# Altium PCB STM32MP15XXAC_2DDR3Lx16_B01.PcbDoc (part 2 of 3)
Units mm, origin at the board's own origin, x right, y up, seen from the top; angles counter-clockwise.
Board outline 89 x 120 mm, 4 copper layers (Top Layer, Signal Layer 1, Signal Layer 2, Bottom Layer), stack 1.571 mm thick; 152 components, 117 nets, 1047 pads, 460 vias.
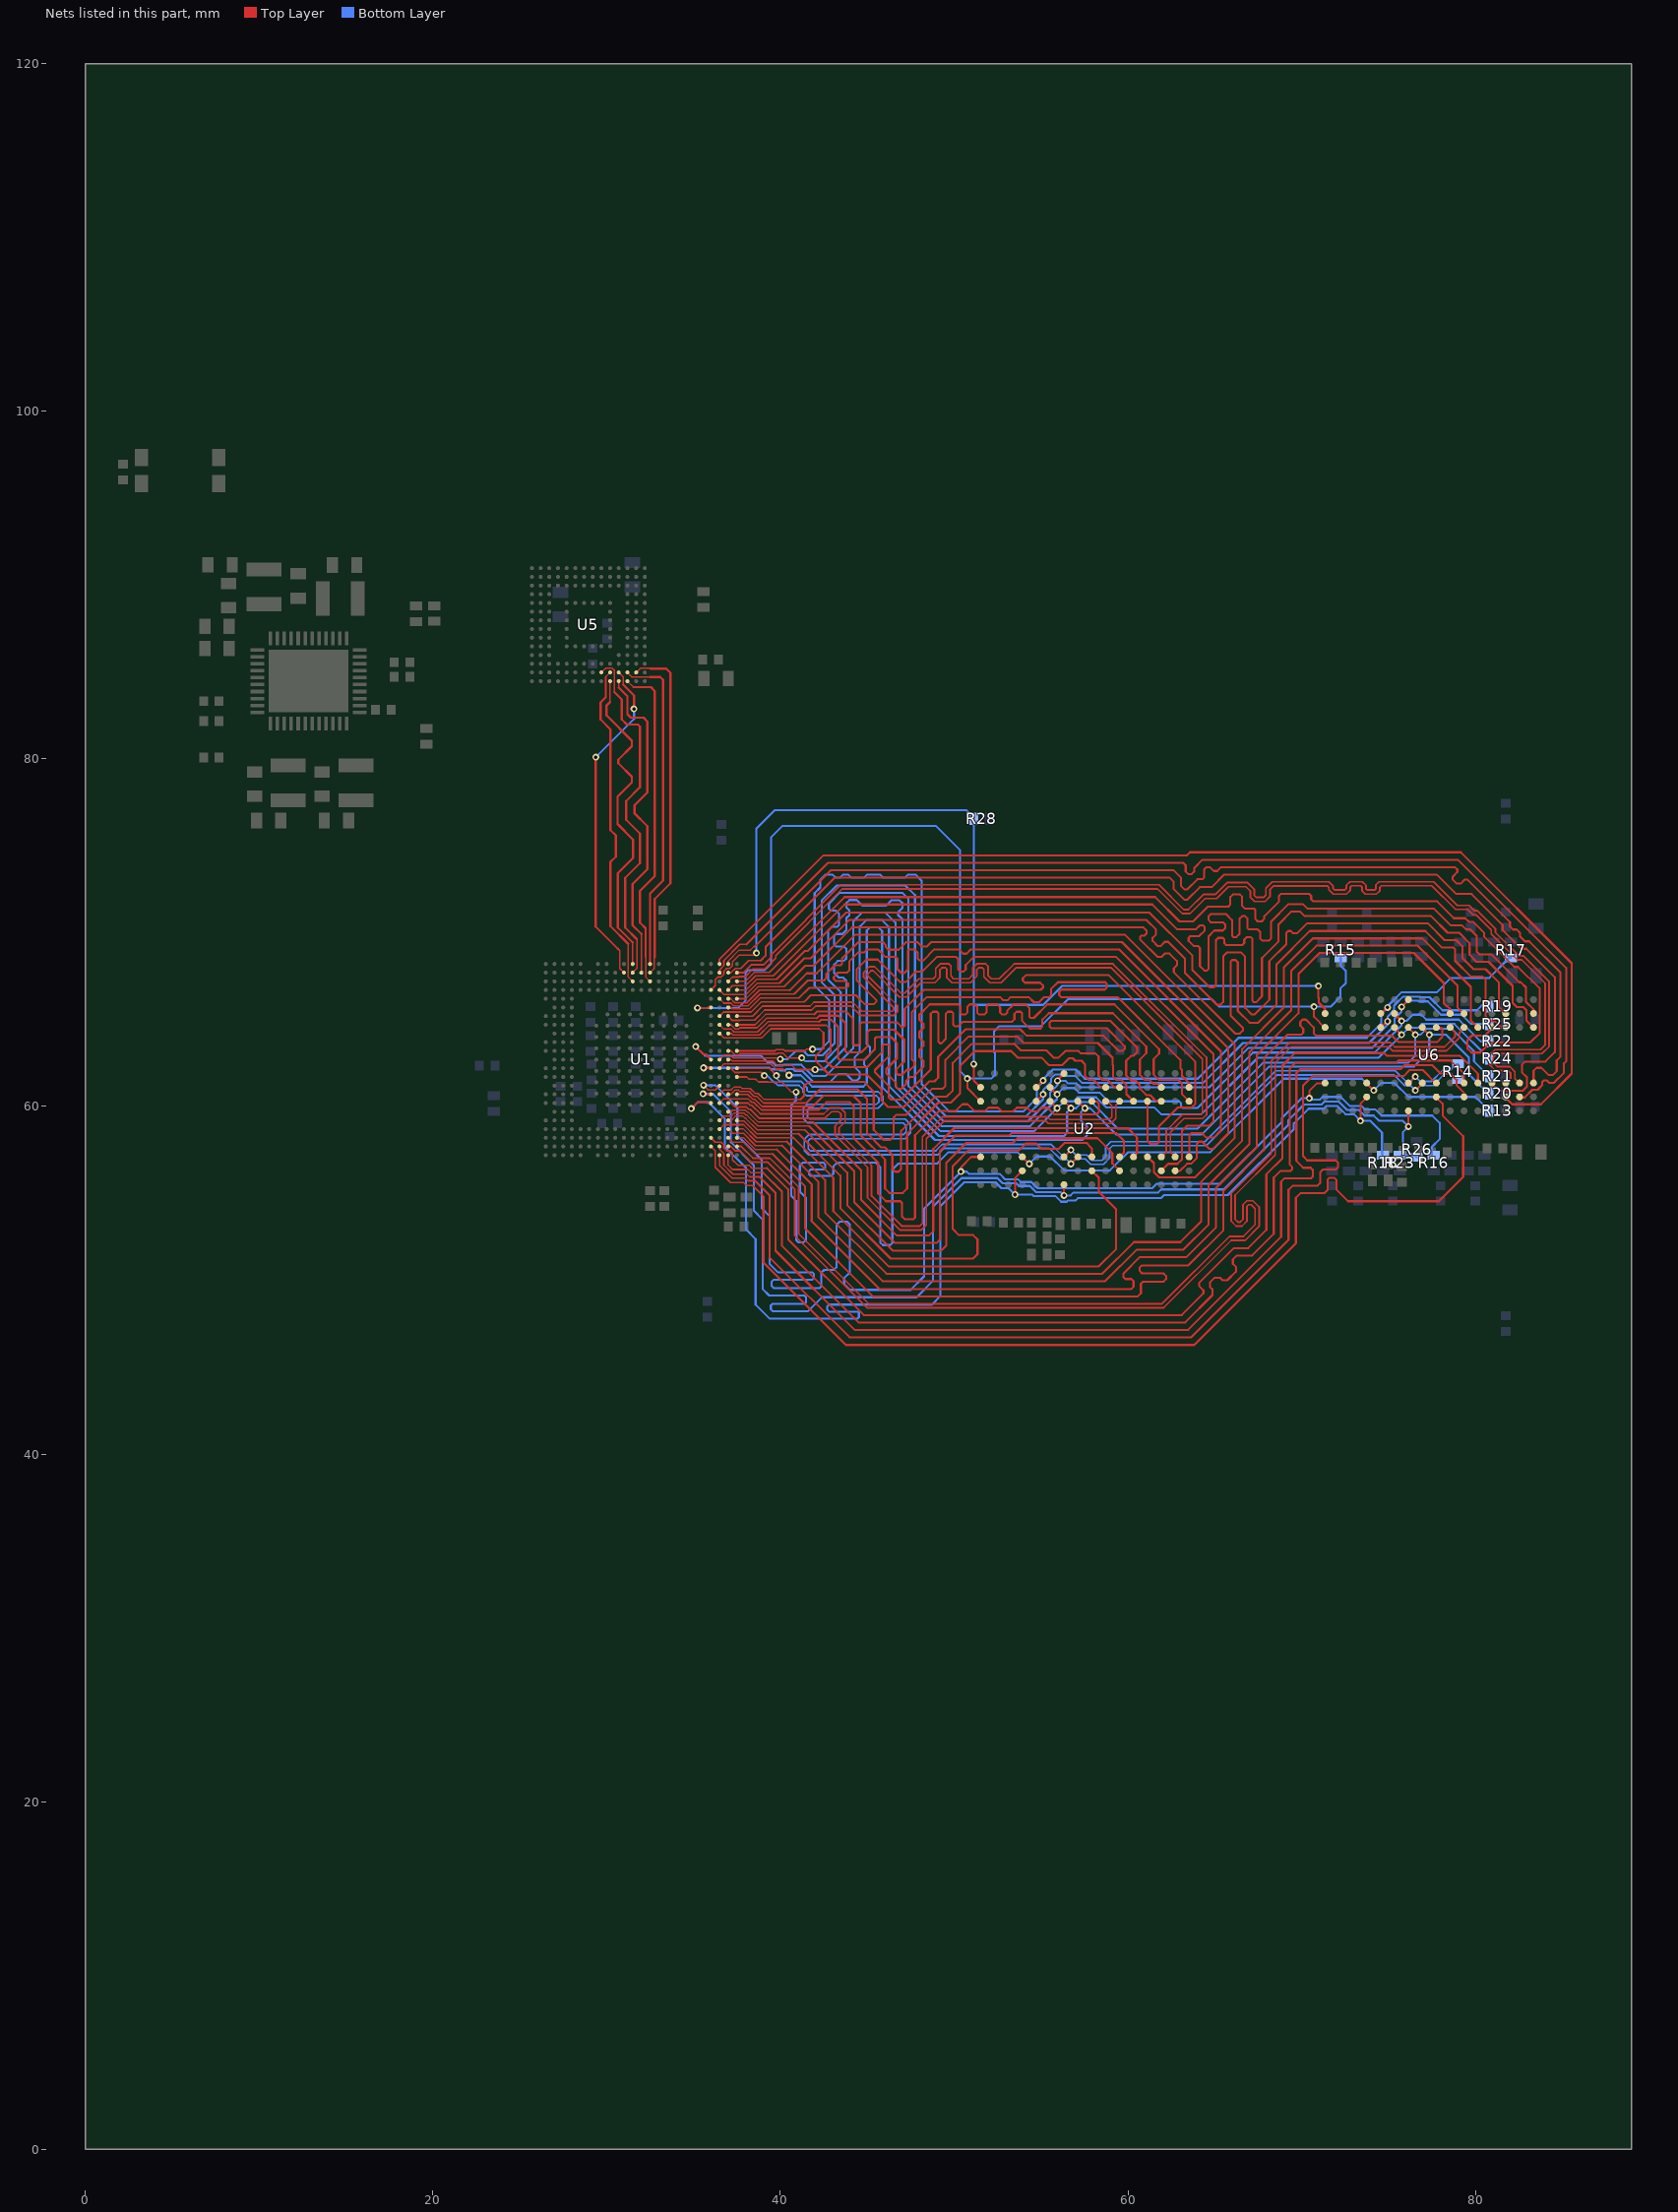
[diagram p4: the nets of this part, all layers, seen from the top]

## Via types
v1: diameter 0.4, hole 0.2, Top Layer to Bottom Layer, tented both sides, 302 vias
v2: diameter 0.6, hole 0.3, Top Layer to Bottom Layer, tented both sides, 80 vias
v3: diameter 0.25, hole 0.1, Top Layer to Signal Layer 1, tented top, 70 vias
v4: diameter 0.25, hole 0.1, Top Layer to Signal Layer 1, tented both sides, 6 vias
v5: diameter 0.25, hole 0.1, Top Layer to Bottom Layer, tented top, 2 vias

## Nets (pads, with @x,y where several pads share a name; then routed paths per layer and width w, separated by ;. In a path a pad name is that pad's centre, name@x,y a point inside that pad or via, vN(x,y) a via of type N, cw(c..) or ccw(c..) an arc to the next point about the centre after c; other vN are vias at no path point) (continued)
DDR_A12: R13.1 U1.P23 U2.N7 U6.N7 | length 74.8
  Top Layer w0.09: U1.P23@37.5,61.7 38.075,61.7 38.2,61.575 38.575,61.575 38.735,61.415 39.288,61.415 39.303,61.4 40.088,61.4 40.52,60.968 40.52,60.93 40.625,60.825 v1(40.9,60.825)
  Top Layer w0.12: U2.N7@53.925,57.1 v1(54.325,56.7) ; U6.N7@73.75,61.325 v1(74.15,60.925)
  Bottom Layer w0.12: v1(40.9,60.825) 40.9,60.35 40.625,60.075 40.625,54.85 40.925,54.55 40.925,52.3 41.05,52.175 41.325,52.175 41.475,52.325 41.475,54.75 41.125,55.1 41.125,56.6 41.3,56.775 42.475,56.775 42.575,56.675 42.575,56.475 42.475,56.375 41.75,56.375 41.65,56.275 41.65,56.1 41.75,56 42.925,56 43.05,56.125 43.05,56.55 43.275,56.775 45.5,56.775 45.75,56.525 45.75,52.175 45.9,52.025 46.325,52.025 46.45,52.15 46.45,56.375 46.8,56.725 49.025,56.725 49.675,57.375 53.65,57.375 v1(54.325,56.7) 54.75,57.125 55.525,57.125 56.325,56.325 58.975,56.325 60.025,57.375 64.75,57.375 68.975,61.6 73.475,61.6 v1(74.15,60.925) 74.575,61.35 75.35,61.35 76.15,60.55 80,60.55 R13.1@80.8,59.75
DDR_A13: R15.1 U1.F20 U2.T3 U6.T3 | length 70.3
  Top Layer w0.09: v1(35.225,65.675) 35.25,65.7 35.437,65.7 35.482,65.655 35.768,65.655 35.813,65.7 U1.F20@36,65.7
  Top Layer w0.12: v1(50.765,61.61) 50.765,61.06 U2.T3@51.525,60.3 ; v1(70.71,65.745) 70.71,65.165 U6.T3@71.35,64.525
  Bottom Layer w0.09: v1(35.225,65.675) 35.245,65.655 35.92,65.655
  Bottom Layer w0.12: 35.92,65.655 37.555,65.655 38,66.1 38,67.7 38.15,67.85 39.1,67.85 39.475,68.225 39.475,75.5 40.125,76.15 48.95,76.15 50.35,74.75 50.35,62.025 v1(50.765,61.61) 52.135,61.61 52.35,61.825 52.35,63.075 52.3,63.125 52.3,64.325 52.6,64.625 55,64.625 56.55,66.175 64.825,66.175 65.255,65.745 v1(70.71,65.745) 71.67,65.745 72.225,66.3 72.225,66.775 72.55,67.1 72.55,67.8 72.25,68.1 R15.1@72.25,68.55
DDR_A14: R16.1 U1.R21 U2.T7 U6.T7 | length 78.8
  Top Layer w0.09: 35.725,61.075 35.85,60.95 36.25,60.95 U1.R21@36.5,61.2
  Top Layer w0.12: v1(50.395,56.25) 50.395,56.51 50.985,57.1 U2.T7@51.525,57.1 ; v1@70.44,60.405 v1(70.44,60.475) 70.44,60.895 70.87,61.325 U6.T7@71.35,61.325
  Bottom Layer w0.12: v1(35.575,61.225) 36.25,61.225 37.525,59.95 37.525,58.325 38.925,56.925 38.925,54.15 39.375,53.7 39.375,50.95 39.875,50.45 41.85,50.45 41.925,50.375 41.925,50.125 41.825,50.025 39.6,50.025 39.5,49.925 39.5,49.675 39.625,49.55 42.25,49.55 42.35,49.65 42.35,50.425 42.525,50.6 43.075,50.6 43.225,50.75 43.225,53.175 43.425,53.375 43.85,53.375 44,53.225 44,50.45 43.675,50.125 43.675,49.775 44,49.45 47.5,49.45 48.275,50.225 48.275,54.13 v1(50.395,56.25) 50.725,56.25 50.85,56.125 52.625,56.125 52.95,55.8 53.689,55.8 53.839,55.65 54.45,55.65 54.8,55.3 61.4,55.3 61.65,55.55 65.3,55.55 68.875,59.125 68.875,59.35 70,60.475 v1(70.44,60.475) 70.51,60.405 71.062,60.405 71.212,60.555 72.245,60.555 72.765,60.035 73.44,60.035 73.65,59.825 74.25,59.825 74.6,59.475 77.525,59.475 77.95,59.05 77.95,58.125 77.5,57.675 R16.1@77.5,57.2
DDR_BA0: R17.1 U1.L23 U2.M2 U6.M2 | length 74.2
  Top Layer w0.09: U1.L23@37.5,63.2 39.697,63.2 39.762,63.265 40.188,63.265 40.253,63.2 41.4,63.2 41.5,63.3 v1(41.85,63.3)
  Top Layer w0.12: U2.M2@54.725,61.1 v1(55.125,61.5) ; U6.M2@74.55,65.325 v1@74.95,65.725
  Bottom Layer w0.12: v1(41.85,63.3) 42.35,63.3 42.8,63.75 42.8,66.125 41.975,66.95 41.975,72.275 42.3,72.6 42.3,73.05 42.6,73.35 43,73.35 43.175,73.175 43.45,73.175 43.625,73.35 43.9,73.35 44.075,73.175 44.825,73.175 45,73.35 45.725,73.35 45.9,73.175 47.175,73.175 47.35,73.35 47.775,73.35 48.125,73 48.125,61.3 49.7,59.725 54,59.725 54.75,60.475 54.75,61.064 55.125,61.439 v1(55.125,61.5) 55.125,61.575 55.675,62.125 57,62.125 57.525,61.6 64.025,61.6 66.375,63.95 73.75,63.95 74.575,64.775 74.575,65.314 v1@74.95,65.689 ; v1(74.95,65.7) 74.95,65.775 75.74,66.565 77.765,66.565 78.6,67.4 80.8,67.4 81.95,68.55 R17.1@82.05,68.55
DDR_BA1: R18.1 U1.U20 U2.N8 U6.N8 | length 69.7
  Top Layer w0.12: v1(34.875,59.875) 35.26,60.26 35.749,60.26 35.809,60.2 U1.U20@36,60.2 ; v1@53.505,54.939 53.505,55.88 U2.N8@53.925,56.3 ; v1(73.39,59.175) 73.39,60.165 U6.N8@73.75,60.525
  Bottom Layer w0.12: v1(34.875,59.875) 35.26,60.26 35.84,60.26 36.8,59.3 36.8,57.7 38.025,56.475 38.025,52.925 38.575,52.375 38.575,48.6 39.375,47.8 44.45,47.8 44.525,47.875 44.525,48.125 44.45,48.2 42.8,48.2 42.7,48.3 42.7,48.5 42.8,48.6 48.725,48.6 49.2,49.075 49.2,54.25 50.59,55.64 52.385,55.64 52.725,55.3 53.135,55.3 v1(53.505,54.93) 54.495,54.93 54.575,54.85 55.825,54.85 56.155,54.52 56.474,54.52 56.554,54.6 57,54.6 57.125,54.725 61.9,54.725 62.075,54.9 65.75,54.9 69.55,58.7 69.55,59.025 70.4,59.875 71.275,59.875 71.425,60.025 72.061,60.025 72.531,59.555 73.01,59.555 v1(73.39,59.175) 73.95,59.175 74.625,58.5 74.625,57.25 R18.1@74.675,57.2
DDR_BA2: R19.1 U1.M21 U2.M3 U6.M3 | length 72.3
  Top Layer w0.09: U1.M21@36.5,62.7 36.75,62.95 37.135,62.95 37.295,62.79 39.935,62.79 v1(40,62.725)
  Top Layer w0.12: U2.M3@54.725,60.3 v1@55.105,60.68 ; U6.M3@74.55,64.525 74.925,64.9 v1(74.95,64.9)
  Bottom Layer w0.12: v1(40,62.725) 40.425,62.725 40.9,63.2 41.334,63.2 41.594,62.94 42.415,62.94 43.125,63.65 43.125,66.4 42.375,67.15 42.375,71.844 43.251,72.72 47.193,72.72 47.75,72.163 47.75,61.225 49.55,59.425 54.125,59.425 55.125,60.425 v1(55.125,60.7) 55.125,60.95 55.59,61.415 55.59,61.624 55.801,61.835 56.099,61.835 56.184,61.75 56.975,61.75 57.375,61.35 64.325,61.35 66.625,63.65 73.875,63.65 74.95,64.725 v1(74.95,64.9) 74.95,65.175 75.325,65.55 75.325,65.809 75.841,66.325 76.798,66.325 76.839,66.285 77.365,66.285 78.11,65.54 80.09,65.54 80.375,65.825 80.725,65.825 R19.1@80.8,65.75
DDR_CASN: R21.1 U1.N20 U2.K3 U6.K3 | length 73.9
  Top Layer w0.09: v1(35.575,62.225) v1@35.6,62.2
  Top Layer w0.12: v1(35.575,62.225) 35.975,62.225 U1.N20@36,62.2 ; U2.K3@56.325,60.3 v1(56.725,59.9) ; U6.K3@76.15,64.525 v1(76.55,64.125)
  Bottom Layer w0.12: v1(35.575,62.225) 39.375,62.225 39.465,62.135 39.924,62.135 39.979,62.08 40.271,62.08 40.351,62.16 40.715,62.16 40.825,62.05 41.25,62.05 41.875,61.425 42.875,61.425 43.325,61.875 43.775,61.875 44.15,61.5 44.4,61.5 44.575,61.675 44.575,61.975 44.275,62.275 44.275,62.825 44.575,63.125 44.575,70.35 44.95,70.725 45.85,70.725 46.25,70.325 46.25,61.175 49.125,58.3 56.325,58.3 56.5,58.475 56.5,59.675 v1(56.725,59.9) 57.016,59.9 57.376,60.26 57.89,60.26 59.425,58.725 64,58.725 67.8,62.525 76.15,62.525 76.55,62.925 v1(76.55,64.125) 76.841,64.125 77.201,64.485 78.615,64.485 79.925,63.175 79.925,62.6 80.775,61.75 R21.1@80.8,61.75
DDR_CKE: R23.1 R26.2 U1.T20 U2.K9 U6.K9 | length 68.8
  Top Layer w0.12: v1(35.55,60.725) 35.575,60.7 U1.T20@36,60.7 ; v1(56.325,54.88) U2.K9@56.325,55.5 ; v1(76.15,58.845) U6.K9@76.15,59.725
  Bottom Layer w0.12: v1(35.55,60.725) 36.125,60.725 37.15,59.7 37.15,57.95 38.475,56.625 38.475,54 38.975,53.5 38.975,49.5 39.35,49.125 41.375,49.125 41.475,49.025 41.475,48.725 41.4,48.65 39.55,48.65 39.45,48.55 39.45,48.325 39.55,48.225 41.6,48.225 42.4,49.025 47.85,49.025 48.775,49.95 48.775,54.225 50.43,55.88 52.495,55.88 52.795,55.58 53.57,55.58 53.725,55.425 54.364,55.425 54.714,55.075 56.13,55.075 v1(56.325,54.88) 56.705,54.88 56.875,55.05 61.75,55.05 61.925,55.225 65.525,55.225 69.225,58.925 69.225,59.2 70.14,60.115 71.14,60.115 71.3,60.275 72.15,60.275 72.63,59.795 73.305,59.795 73.625,59.475 74.15,59.475 74.45,59.175 75.82,59.175 v1(76.15,58.845) 75.825,58.52 R23.1@75.825,57.2 ; R23.1@75.75,57.2 R23.1@75.825,57.2 ; R26.2@76.625,57.075 76.5,57.2 R23.1@75.825,57.2
DDR_CLK_N: R14.2 U1.N23 U2.K7 U6.K7 | length 70.4
  Top Layer w0.1: U1.N23@37.5,62.2 39.375,62.2 39.775,61.8 v1(39.775,61.775) ; U2.K7@56.325,57.1 v1(56.725,57.5) ; U6.K7@76.15,61.325 v1(76.55,61.725)
  Bottom Layer w0.1: v1(39.775,61.775) 39.775,61.625 39.95,61.45 41.17,61.45 41.53,61.09 41.53,60.92 41.6,60.85 45.625,60.85 45.905,60.57 45.905,60.18 45.62,59.895 41.645,59.895 41.555,59.805 41.555,59.395 41.675,59.275 47.175,59.275 47.475,58.975 47.475,58.45 47.175,58.15 41.725,58.15 41.605,58.03 41.605,57.57 41.725,57.45 48.95,57.45 49.325,57.825 55.575,57.825 56.175,57.225 56.45,57.225 v1(56.725,57.5) 57.01,57.215 57.645,57.215 57.955,56.905 58.505,56.905 58.72,57.12 58.72,57.67 59.03,57.98 64.43,57.98 68.5,62.05 75.4,62.05 76,61.45 76.275,61.45 v1(76.55,61.725) 76.835,61.44 77.47,61.44 78.155,62.125 78.6,62.125 78.925,62.45 R14.2@79,62.45
DDR_CLK_P: R14.1 U1.N22 U2.J7 U6.J7 | length 70.9
  Top Layer w0.1: U1.N22@37,62.2 37.15,62.2 37.4,61.95 37.605,61.95 37.625,61.97 38.88,61.97 v1(39.075,61.775) ; v1(56.725,56.7) U2.J7@57.125,57.1 ; v1(76.55,60.925) U6.J7@76.95,61.325
  Bottom Layer w0.1: v1(39.075,61.775) 39.25,61.775 39.395,61.63 39.395,61.618 39.618,61.395 39.68,61.395 39.855,61.22 41.075,61.22 41.3,60.995 41.3,60.825 41.505,60.62 45.53,60.62 45.675,60.475 45.675,60.275 45.525,60.125 41.55,60.125 41.325,59.9 41.325,59.3 41.58,59.045 47.08,59.045 47.245,58.88 47.245,58.545 47.08,58.38 41.63,58.38 41.375,58.125 41.375,57.475 41.63,57.22 49.045,57.22 49.42,57.595 55.48,57.595 56.1,56.975 56.45,56.975 v1(56.725,56.7) 57.01,56.985 57.55,56.985 57.86,56.675 58.6,56.675 58.95,57.025 58.95,57.575 59.125,57.75 64.525,57.75 68.595,61.82 75.305,61.82 75.925,61.2 76.275,61.2 v1(76.55,60.925) 76.835,61.21 77.565,61.21 78.25,61.895 78.605,61.895 78.95,61.55 R14.1@79,61.55
DDR_CSN: R22.1 U1.M22 U2.L2 U6.L2 | length 72.9
  Top Layer w0.09: U1.M22@37,62.7 37.145,62.7 37.225,62.62 39.567,62.62 39.812,62.375 40.65,62.375 40.9,62.125 v1(42,62.125)
  Top Layer w0.12: U2.L2@55.525,61.1 v1(55.925,60.7) ; U6.L2@75.35,65.325 v1(75.75,64.925)
  Bottom Layer w0.12: v1(42,62.125) 42.475,62.125 43.8,63.45 43.8,67.225 43.6,67.425 43.35,67.425 43.1,67.675 43.1,68.175 43.3,68.375 43.65,68.375 43.8,68.525 43.8,69.075 43.675,69.2 43.225,69.2 43.1,69.325 43.1,69.825 43.2,69.925 43.575,69.925 43.8,70.15 43.8,70.844 43.975,71.019 43.975,71.275 43.8,71.45 43.8,71.705 43.975,71.88 44.395,71.88 44.705,71.57 46.1,71.57 46.405,71.875 46.85,71.875 47.025,71.7 47.025,71.425 46.775,71.175 46.775,71.019 47.025,70.769 47.025,61.125 49.275,58.875 54.375,58.875 55.925,60.425 v1(55.925,60.7) 56.285,61.06 56.915,61.06 57.175,60.8 58.375,60.8 58.875,60.3 62.95,60.3 63.05,60.2 63.05,60.025 63.15,59.925 64.025,59.925 67.2,63.1 74.2,63.1 75.75,64.65 v1(75.75,64.925) 76.041,64.925 76.401,65.285 76.89,65.285 77.175,65 79.05,65 80.3,63.75 R22.1@80.8,63.75
DDR_DQ0: U1.E22 U2.D7 | length 45.6
  Top Layer w0.09: U1.E22@37,66.2 37.15,66.2 37.39,65.96 38.06,65.96 38.8,66.7 40.55,66.7
  Top Layer w0.12: 40.55,66.7 41.51,67.66 42.085,67.66 44.305,69.88 59.837,69.88 66.15,63.567 66.15,58.196 63.874,55.92 61.796,55.92 61.503,56.213 61.503,56.744 61.148,57.1 U2.D7@61.125,57.1
DDR_DQ1: U1.F22 U2.A7 | length 45.3
  Top Layer w0.09: U1.F22@37,65.7 37.169,65.7 37.249,65.62 38.22,65.62 38.85,66.25 41.075,66.25
  Top Layer w0.12: 41.075,66.25 41.645,66.82 43.795,66.82 43.9,66.925 43.9,67.064 43.739,67.225 43.2,67.225 43.075,67.35 43.075,67.456 43.319,67.7 43.84,67.7 43.965,67.825 43.965,68.346 44.494,68.875 44.825,68.875 44.99,69.04 45.609,69.04 46.049,68.6 46.65,68.6 46.749,68.501 46.749,67.9 46.975,67.675 47.134,67.675 47.342,67.883 47.342,68.958 47.424,69.04 47.725,69.04 47.9,68.865 47.9,68.525 48.023,68.402 48.223,68.402 48.861,69.04 50.274,69.04 50.519,68.794 50.721,68.794 50.966,69.04 59.489,69.04 65.355,63.174 65.355,58.62 64.945,58.21 64.525,58.21 64.265,58.47 63.665,58.47 63.535,58.34 U2.A7@63.535,57.1
DDR_DQ2: U1.H21 U2.A3 | length 45.7
  Top Layer w0.09: U1.H21@36.5,64.7 36.75,64.45 37.17,64.45 37.33,64.29 38.69,64.29 39.275,64.875 42.225,64.875
  Top Layer w0.12: 42.225,64.875 42.325,64.975 42.936,64.975 43.32,64.591 43.32,62.775 43.41,62.685 44.823,62.685 45.44,63.302 45.44,63.91 45.525,63.995 46.374,63.995 46.72,63.649 46.72,62.776 46.097,62.153 46.097,61.91 46.665,61.342 46.665,61.1 46.74,61.025 46.968,61.025 47.243,61.3 47.243,61.474 47.459,61.691 47.634,61.691 48.24,62.297 48.24,62.625 47.995,62.87 47.995,63.25 48.24,63.495 48.24,63.725 47.995,63.97 47.995,64.275 48.24,64.52 48.24,64.755 47.995,65 47.995,65.269 48.601,65.875 50.25,65.875 50.37,65.755 50.37,65.37 50.45,65.29 50.64,65.29 50.775,65.425 50.775,65.75 50.9,65.875 51.2,65.875 51.325,65.75 51.325,65.39 51.425,65.29 51.74,65.29 51.875,65.425 51.875,65.775 51.975,65.875 52.475,65.875 52.65,65.7 52.65,65.4 52.76,65.29 52.95,65.29 53.055,65.395 53.055,65.504 53.426,65.875 54.125,65.875 54.325,65.675 54.325,65.175 54.4,65.1 54.587,65.1 55.362,65.875 59.231,65.875 61.8,63.306 61.8,63.04 61.485,62.725 61.485,61.831 61.776,61.54 62.887,61.54 63.125,61.302 63.125,60.7 U2.A3@63.525,60.3
DDR_DQ3: U1.E21 U2.B8 | length 44.1
  Top Layer w0.09: U1.E21@36.5,66.2 36.75,65.95 37.16,65.95 37.32,65.79 38.14,65.79 38.825,66.475 40.8,66.475
  Top Layer w0.12: 40.8,66.475 41.565,67.24 42.495,67.24 42.655,67.4 42.655,67.63 43.15,68.125 43.47,68.125 43.545,68.2 43.545,68.52 44.485,69.46 45.9,69.46 46.075,69.285 46.075,69.168 46.223,69.02 46.81,69.02 47.25,69.46 47.899,69.46 48.154,69.204 48.431,69.204 48.687,69.46 59.663,69.46 65.775,63.348 65.775,58.446 64.904,57.575 64.675,57.575 64.275,57.975 64.1,57.975 63.975,57.85 63.975,57.041 63.644,56.71 63.415,56.71 63.005,56.3 U2.B8@62.725,56.3
DDR_DQ4: U1.J21 U2.C3 | length 46.2
  Top Layer w0.09: U1.J21@36.5,64.2 36.75,63.95 38.925,63.95 39.45,64.475 42.248,64.475 42.48,64.243
  Top Layer w0.12: 42.48,64.243 42.48,63.355 42.05,62.925 42.05,62.6 42.805,61.845 44.974,61.845 45.825,60.994 45.825,60.351 46.201,59.975 47.106,59.975 48.576,61.445 48.87,61.445 49.08,61.655 49.08,62.858 50.67,64.448 51.95,64.448 ; 51.95,64.45 53.801,64.45 54.181,64.07 58.605,64.07 59.475,63.2 59.7,63.2 59.825,63.325 59.825,63.475 58.8,64.5 55.6,64.5 55.5,64.6 55.5,64.825 55.6,64.925 58.993,64.925 60.534,63.384 60.534,63.133 60.311,62.91 60.176,62.91 59.9,62.634 59.9,61.785 60.2,61.485 60.449,61.485 60.685,61.249 60.685,61.031 61.056,60.66 61.274,60.66 61.485,60.449 61.485,60.44 61.494,60.44 61.634,60.3 U2.C3@61.925,60.3
DDR_DQ5: U1.J22 U2.C2 | length 45.2
  Top Layer w0.09: U1.J22@37,64.2 37.18,64.2 37.26,64.12 38.795,64.12 39.35,64.675 42.642,64.675 42.775,64.542
  Top Layer w0.12: 42.775,64.542 42.9,64.417 42.9,63.181 42.634,62.916 42.634,62.609 42.979,62.265 44.997,62.265 45.86,63.128 45.86,63.485 45.95,63.575 46.2,63.575 46.3,63.475 46.3,62.95 45.444,62.094 45.444,61.969 46.245,61.168 46.245,60.525 46.375,60.395 46.932,60.395 48.66,62.123 48.66,65.34 48.775,65.455 49.02,65.455 49.1,65.375 49.1,63.725 49.189,63.636 49.264,63.636 ; 49.275,63.647 49.525,63.897 49.525,65.33 49.65,65.455 49.87,65.455 49.95,65.375 49.95,64.7 50.025,64.625 50.253,64.625 50.498,64.87 53.325,64.87 53.475,65.02 53.475,65.33 53.6,65.455 53.825,65.455 53.905,65.375 53.905,64.94 54.355,64.49 54.975,64.49 55.08,64.595 55.08,64.999 55.451,65.37 59.142,65.37 61.065,63.447 61.065,63.07 60.695,62.7 60.695,61.821 60.976,61.54 61.23,61.54 61.23,61.535 61.445,61.32 61.705,61.32 U2.C2@61.925,61.1
DDR_DQ6: U1.H22 U2.A2 | length 46.3
  Top Layer w0.09: U1.H22@37,64.7 37.161,64.7 37.401,64.46 37.599,64.46 37.669,64.53 38.655,64.53 39.2,65.075 42.1,65.075
  Top Layer w0.12: 42.1,65.075 42.25,65.225 43.325,65.225 43.74,64.81 43.74,63.19 43.825,63.105 44.649,63.105 45.02,63.476 45.02,64.285 45.15,64.415 46.548,64.415 47.14,63.823 47.14,62.602 46.675,62.138 46.675,61.925 46.776,61.825 47,61.825 47.288,62.112 47.462,62.112 47.723,62.374 47.723,62.548 47.575,62.696 47.575,65.443 48.427,66.295 52.649,66.295 52.834,66.109 53.067,66.109 53.252,66.295 54.299,66.295 54.591,66.003 54.897,66.003 55.188,66.295 55.475,66.295 55.575,66.395 55.575,66.75 55.975,67.15 58.706,67.15 58.775,67.081 58.775,66.825 58.675,66.725 56.2,66.725 56.05,66.575 56.05,66.4 56.155,66.295 59.405,66.295 63.025,62.675 63.025,62.2 63.115,62.11 63.115,61.76 63.525,61.35 U2.A2@63.525,61.1
DDR_DQ7: U1.G21 U2.C8 | length 46.6
  Top Layer w0.09: U1.G21@36.5,65.2 36.74,65.44 38.315,65.44 38.9,66.025 41.375,66.025
  Top Layer w0.12: 41.375,66.025 41.75,66.4 44.355,66.4 44.87,65.885 45.375,65.885 45.535,66.045 45.535,66.11 44.385,67.26 44.385,67.885 44.955,68.455 45.6,68.455 46.894,67.161 47.214,67.161 47.818,67.765 48.18,67.765 49.035,68.62 50.1,68.62 50.225,68.495 50.225,67.9 50.36,67.765 50.55,67.765 50.665,67.88 50.665,68.145 51.14,68.62 59.315,68.62 64.935,63 64.935,59.17 64.655,58.89 63.4,58.89 63.115,58.605 63.115,56.96 62.855,56.7 62.325,56.7 U2.C8@61.925,56.3
DDR_DQ8: U1.T21 U2.E3 | length 34.2
  Top Layer w0.09: U1.T21@36.5,60.7 36.75,60.95 37.16,60.95 37.32,61.11 37.73,61.11 37.8,61.04 38.27,61.04 38.555,60.755 38.72,60.755 39.075,60.4 41.15,60.4
  Top Layer w0.12: 41.15,60.4 41.375,60.625 41.375,61.175 41.625,61.425 44.8,61.425 45.375,60.85 45.375,58.65 45.95,58.075 46.3,58.075 46.525,58.3 46.525,59.375 46.675,59.525 47.25,59.525 48.75,61.025 49.35,61.025 49.5,61.175 49.5,62.684 50.844,64.028 53.628,64.028 54.007,63.65 58.27,63.65 59.12,62.8 59.12,62.39 59.145,62.365 59.145,61.71 59.315,61.54 59.609,61.54 59.915,61.234 59.915,60.71 U2.E3@60.325,60.3
DDR_DQ9: U1.U21 U2.H3 | length 35
  Top Layer w0.09: U1.U21@36.5,60.2 36.75,60.45 38.138,60.45 38.343,60.245 38.465,60.245 38.91,59.8 42.2,59.8
  Top Layer w0.12: 42.2,59.8 42.65,60.25 44,60.25 44.225,60.025 44.225,58.175 45.625,56.775 45.625,55 46.075,54.55 46.9,54.55 47,54.45 47,53.675 47.15,53.525 47.675,53.525 47.75,53.6 47.75,58.35 49.15,59.75 50.1,59.75 50.475,60.125 50.775,60.125 51.15,59.75 51.8,59.75 51.979,59.929 52.525,59.929 52.729,59.725 53.4,59.725 53.604,59.929 54.2,59.929 54.404,59.725 54.85,59.725 55.054,59.929 55.387,59.929 55.776,59.54 58.19,59.54 58.325,59.675 58.325,60.175 58.225,60.275 57.95,60.275 U2.H3@57.925,60.3
DDR_DQ10: U1.T22 U2.F2 | length 34.1
  Top Layer w0.09: U1.T22@37,60.7 37.15,60.7 37.39,60.94 37.599,60.94 37.669,60.87 38.199,60.87 38.484,60.585 38.64,60.585 39.025,60.2 41.5,60.2
  Top Layer w0.12: 41.5,60.2 42.3,61 44.425,61 45,60.425 45,58.45 45.8,57.65 46.025,57.65 46.45,57.225 46.45,56.4 46.6,56.25 46.8,56.25 46.95,56.4 46.95,58.6 48.925,60.575 49.575,60.575 49.925,60.925 49.925,62.515 51.015,63.605 53.451,63.605 ; 53.454,63.608 53.833,63.23 55.305,63.23 55.725,62.81 56.015,62.81 56.4,63.195 57.154,63.195 57.299,63.05 58.139,63.05 58.315,62.874 58.315,61.77 58.555,61.53 58.819,61.53 59.249,61.1 U2.F2@59.525,61.1
DDR_DQ11: U1.W21 U2.F7 | length 34.4
  Top Layer w0.09: U1.W21@36.5,59.2 36.75,59.45 37.16,59.45 37.32,59.61 37.918,59.61 38.033,59.495 38.08,59.495 38.7,58.875 41.65,58.875
  Top Layer w0.12: 41.65,58.875 44.25,56.275 44.25,54.5 46.6,52.15 49,52.15 49.175,52.325 49.175,57.425 50.08,58.33 53.165,58.33 53.295,58.46 59.34,58.46 59.775,58.025 59.775,57.35 U2.F7@59.525,57.1
DDR_DQ12: U1.W23 U2.H7 | length 33.9
  Top Layer w0.09: U1.W23@37.5,59.2 37.545,59.155 37.92,59.155 38.65,58.425 41.05,58.425
  Top Layer w0.12: 41.05,58.425 43.45,56.025 43.45,54.15 46.35,51.25 51.1,51.25 51.35,51.5 51.35,52.35 51.1,52.6 50.275,52.6 49.925,52.95 49.925,56.575 50.835,57.485 53.75,57.485 54.125,57.86 54.725,57.86 55.015,57.57 56.035,57.57 56.368,57.903 57.652,57.903 57.925,57.58 U2.H7@57.925,57.1
DDR_DQ13: U1.T23 U2.G2 | length 33.9
  Top Layer w0.09: U1.T23@37.5,60.7 38.129,60.7 38.414,60.415 38.535,60.415 38.95,60 41.85,60
  Top Layer w0.12: 41.85,60 42.475,60.625 44.2,60.625 44.625,60.2 44.625,58.35 46.025,56.95 46.025,55.275 46.275,55.025 47.05,55.025 47.3,55.275 47.3,58.425 49.1,60.225 49.825,60.225 50.345,60.745 50.345,62.341 51.189,63.185 53.284,63.185 53.659,62.81 55.023,62.81 55.455,62.378 56.218,62.378 56.615,62.775 56.825,62.775 56.97,62.63 57.335,62.63 57.535,62.43 57.535,61.75 57.745,61.54 58.015,61.54 58.455,61.1 U2.G2@58.725,61.1
DDR_DQ14: U1.W22 U2.F8 | length 33.5
  Top Layer w0.09: U1.W22@37,59.2 37.161,59.2 37.401,59.44 37.847,59.44 37.962,59.325 38,59.325 38.675,58.65 41.4,58.65
  Top Layer w0.12: 41.4,58.65 43.85,56.2 43.85,54.325 46.475,51.7 49.25,51.7 49.55,52 49.55,56.75 50.705,57.905 53.38,57.905 53.65,58.175 58.25,58.175 59.105,57.32 59.105,56.72 U2.F8@59.525,56.3
DDR_DQ15: U1.Y21 U2.H8 | length 32.9
  Top Layer w0.09: U1.Y21@36.5,58.7 36.75,58.95 37.885,58.95 38.635,58.2 40.625,58.2
  Top Layer w0.12: 40.625,58.2 40.75,58.2 43.05,55.9 43.05,53.975 46.225,50.8 58.325,50.8 59.325,51.8 59.325,54.08 58.325,55.08 58.325,55.9 U2.H8@57.925,56.3
DDR_DQ16: U1.B22 U6.D7 | length 64.3
  Top Layer w0.09: U1.B22@37,67.7 37.161,67.7 37.411,67.95 37.725,67.95 38.175,68.4 38.875,68.4
  Top Layer w0.12: 38.875,68.4 39.15,68.675 39.15,69.175 43.15,73.175 62.4,73.175 62.625,72.95 62.625,72.525 63.25,71.9 63.425,71.9 64.15,72.625 64.825,72.625 65.55,73.35 77.775,73.35 78.9,72.225 79.782,72.225 81.57,70.437 81.57,70.155 82.645,69.08 82.927,69.08 84.575,67.432 84.575,63.125 84.035,62.585 82.86,62.585 82.675,62.4 82.675,61.975 82.97,61.68 82.97,61.145 82.74,60.915 81.36,60.915 U6.D7@80.95,61.325
DDR_DQ17: U1.D22 U6.A2 | length 65.9
  Top Layer w0.09: U1.D22@37,66.7 37.25,66.95 38,66.95 38.575,67.525 39.6,67.525
  Top Layer w0.12: 39.6,67.525 43.7,71.625 61.4,71.625 62.825,70.2 63.925,70.2 64.15,70.425 64.325,70.425 64.425,70.325 64.425,70.125 64.1,69.8 63.6,69.8 63.5,69.7 63.5,69.525 63.8,69.225 64.05,69.225 64.15,69.125 64.15,68.075 64.4,67.825 64.55,67.825 64.649,67.924 64.649,69.799 64.975,70.125 65.475,70.125 65.6,70.25 65.6,70.475 65.475,70.6 64.774,70.6 64.649,70.725 64.649,70.95 64.774,71.075 65.65,71.075 66,70.725 66,69.825 66.075,69.75 66.25,69.75 66.425,69.925 66.425,70.8 66.575,70.95 66.75,70.95 66.875,70.825 66.875,70.275 66.95,70.2 67.45,70.2 67.625,70.025 67.625,69.65 67.725,69.55 68.125,69.55 68.25,69.675 68.25,70.65 69.25,71.65 70.075,71.65 70.35,71.375 77.625,71.375 78.586,70.414 79.241,70.414 79.45,70.205 79.686,70.205 80.09,69.801 80.09,68.905 80.25,68.745 80.935,68.745 82.529,67.151 82.609,67.151 82.91,66.85 82.91,66.026 83.35,65.586 U6.A2@83.35,65.325
DDR_DQ18: U1.D23 U6.A3 | length 65
  Top Layer w0.09: U1.D23@37.5,66.7 38.025,66.7 38.65,67.325 39.775,67.325
  Top Layer w0.12: 39.775,67.325 41.4,68.95 41.575,68.95 43.775,71.15 61.25,71.15 63.7,68.7 63.7,67.875 64.725,66.85 64.925,66.85 65.069,66.994 65.069,69.569 65.2,69.7 65.475,69.7 65.55,69.625 65.55,69.4 65.65,69.3 66.6,69.3 66.7,69.4 66.7,69.6 66.85,69.75 67.07,69.75 67.17,69.65 67.17,66.08 67.25,66 67.375,66 67.72,66.345 67.72,68.545 68.675,69.5 68.675,70.475 69.425,71.225 69.9,71.225 70.175,70.95 77.451,70.95 78.407,69.994 79.067,69.994 79.67,69.391 79.67,68.731 80.076,68.325 80.761,68.325 82.15,66.936 82.15,65.965 82.4,65.715 82.77,65.715 82.94,65.545 82.94,64.935 U6.A3@83.35,64.525
DDR_DQ19: U1.B21 U6.B8 | length 64.6
  Top Layer w0.09: U1.B21@36.5,67.7 36.5,67.861 36.75,68.111 36.75,68.4 37.675,69.325 38.05,69.325
  Top Layer w0.12: 38.05,69.325 42.75,74.025 63.175,74.025 63.325,73.875 63.325,73.525 63.475,73.375 63.675,73.375 63.825,73.525 63.825,73.725 64.3,74.2 78.995,74.2 85.225,67.97 85.225,62.6 85.1,62.475 ; U6.B8@82.55,60.525 82.841,60.525 83.281,60.965 83.59,60.965 83.85,61.225 83.85,61.4 83.95,61.5 84.125,61.5 84.275,61.35 84.5,61.35 85.1,61.95 85.1,62.475 ; 85.1,62.481 85.1,62.475
DDR_DQ20: U1.A21 U6.C8 | length 65.6
  Top Layer w0.12: U1.A21@36.5,68.2 36.5,68.475 42.475,74.45 63.4,74.45 63.575,74.625 79.164,74.625 85.55,68.239 85.55,61.896 83.779,60.125 82.12,60.125 81.75,60.495 U6.C8@81.75,60.525
DDR_DQ21: U1.E23 U6.C3 | length 65.9
  Top Layer w0.09: U1.E23@37.5,66.2 38.025,66.2 38.725,66.9 40.225,66.9
  Top Layer w0.12: 40.225,66.9 41.425,68.1 41.925,68.1 44.125,70.3 60.9,70.3 61.075,70.125 61.075,69.95 60.95,69.825 60.775,69.825 60.7,69.75 60.7,69.625 61.725,68.6 61.925,68.6 62.125,68.8 62.4,68.8 62.825,68.375 62.825,68.125 62.65,67.95 62.65,67.725 66.175,64.2 66.45,64.2 66.625,64.375 66.625,64.525 65.91,65.24 65.91,68.335 66,68.425 66.2,68.425 66.33,68.295 66.33,65.495 67,64.825 67.504,64.825 68.56,65.881 68.56,68.185 70.47,70.095 77.118,70.095 78.059,69.154 78.719,69.154 78.83,69.043 78.83,68.383 79.728,67.485 80.413,67.485 80.58,67.318 80.58,65.185 80.87,64.895 81.14,64.895 81.51,64.525 U6.C3@81.75,64.525
DDR_DQ22: U1.D21 U6.C2 | length 63.8
  Top Layer w0.09: U1.D21@36.5,66.7 36.75,66.45 38.025,66.45 38.675,67.1 39.95,67.1
  Top Layer w0.12: 39.95,67.1 41.375,68.525 41.75,68.525 43.95,70.725 61.075,70.725 61.625,70.175 61.625,69.9 61.425,69.7 61.425,69.525 61.725,69.225 61.875,69.225 62.125,69.475 62.325,69.475 63.275,68.525 63.275,67.7 65.125,65.85 65.325,65.85 65.489,66.014 65.489,68.639 65.725,68.875 66.5,68.875 66.75,68.625 66.75,65.675 67.125,65.3 67.3,65.3 68.14,66.14 68.14,68.365 69.125,69.35 69.125,70 69.225,70.1 69.375,70.1 69.5,69.975 69.75,69.975 70.3,70.525 77.282,70.525 78.233,69.574 78.893,69.574 79.25,69.217 79.25,68.557 79.902,67.905 80.587,67.905 81.363,67.129 81.363,66.798 ; 81.36,66.798 81.36,65.715 U6.C2@81.75,65.325
DDR_DQ23: U1.A22 U6.A7 | length 63.8
  Top Layer w0.09: U1.A22@37,68.2 37,68.375 37.625,69 38.275,69 38.475,69.2
  Top Layer w0.12: 38.475,69.2 38.525,69.2 42.925,73.6 62.625,73.6 63.05,73.175 63.05,72.7 63.25,72.5 63.425,72.5 64,73.075 64.3,73.075 64.4,73.175 64.4,73.65 64.525,73.775 64.725,73.775 64.95,73.55 65.15,73.55 65.375,73.775 78.826,73.775 78.963,73.638 78.963,73.488 78.7,73.225 78.7,73.05 78.925,72.825 79.15,72.825 79.375,73.05 79.551,73.05 81.99,70.611 81.99,70.363 82.169,70.184 82.381,70.184 82.572,69.993 82.572,69.781 82.853,69.5 83.101,69.5 84.9,67.701 84.9,62.875 84.68,62.655 84.68,62.03 84.455,61.805 84.22,61.805 83.8,62.225 83.525,62.225 83.35,62.05 U6.A7@83.35,61.325
DDR_DQ24: U1.Y23 U6.E3 | length 64.2
  Top Layer w0.09: U1.Y23@37.5,58.7 37.875,58.7 38.6,57.975 40.375,57.975
  Top Layer w0.12: 40.375,57.975 42.575,55.775 42.575,53.9 46.1,50.375 58.525,50.375 60.35,52.2 63.025,52.2 64.225,53.4 64.225,55.675 66.58,58.03 66.58,63.307 68.98,65.707 68.98,68.005 70.65,69.675 76.944,69.675 79.739,66.88 ; 79.75,66.88 79.75,64.925 U6.E3@80.15,64.525
DDR_DQ25: U1.Y22 U6.F2 | length 63.3
  Top Layer w0.09: U1.Y22@37,58.7 37.25,58.45 37.875,58.45 38.575,57.75 40.1,57.75
  Top Layer w0.12: 40.1,57.75 42.175,55.675 42.175,53.65 45.875,49.95 58.7,49.95 60.5,51.75 63.175,51.75 64.65,53.225 64.65,55.5 67,57.85 67,63.133 69.4,65.533 69.4,67.8 70.855,69.255 76.68,69.255 78.97,66.965 ; 78.981,66.9 78.981,66.954 78.97,66.965 ; U6.F2@79.35,65.325 78.97,65.705 78.97,66.965
DDR_DQ26: U1.AB21 U6.F8 | length 64
  Top Layer w0.09: U1.AB21@36.5,57.7 36.5,57.539 36.75,57.289 36.75,56.625 37.275,56.1 38.075,56.1 38.225,55.95 38.8,55.95
  Top Layer w0.12: 38.8,55.95 39.725,55.025 39.725,51.7 44.275,47.15 63.475,47.15 68.825,52.5 68.825,55.675 69.025,55.875 70.55,55.875 70.65,55.975 70.65,56.35 70.525,56.475 70.1,56.475 69.7,56.875 69.7,61.922 69.923,62.15 75.7,62.15 75.925,62.375 77.51,62.375 77.989,61.896 78.531,61.896 78.91,61.517 78.91,61.226 79.35,60.786 U6.F8@79.35,60.525
DDR_DQ27: U1.AB20 U6.H8 | length 63.4
  Top Layer w0.09: U1.AB20@36,57.7 36.25,57.45 36.25,56.5 37.125,55.625 37.875,55.625 38.05,55.45 38.4,55.45
  Top Layer w0.12: 38.4,55.45 39.025,54.825 39.025,51.025 43.775,46.275 63.825,46.275 69.675,52.125 69.675,54.75 69.95,55.025 71.325,55.025 71.5,55.2 71.5,55.8 71.6,55.9 71.875,55.9 72,55.775 72,55.225 72.675,54.55 77.9,54.55 79.3,55.95 79.3,58.295 78.12,59.475 78.12,60.155 U6.H8@77.75,60.525
DDR_DQ28: U1.AC22 U6.F7 | length 62.5
  Top Layer w0.09: U1.AC22@37,57.2 37,56.625 37.25,56.375 38.125,56.375 38.3,56.2 39,56.2
  Top Layer w0.12: 39,56.2 40.1,55.1 40.1,51.975 44.5,47.575 63.3,47.575 64.875,49.15 64.875,49.475 64.725,49.625 64.725,49.875 65,50.15 65.3,50.15 65.45,50 65.725,50 66.225,50.5 66.225,50.775 66.05,50.95 66.05,51.2 66.275,51.425 67.15,51.425 68.4,52.675 68.4,55.915 68.785,56.3 69.375,56.3 69.45,56.375 69.45,56.525 69.31,56.665 69.31,62.176 69.659,62.525 75.45,62.525 75.575,62.65 78.575,62.65 79.35,61.875 U6.F7@79.35,61.325
DDR_DQ29: U1.AC21 U6.H7 | length 63.3
  Top Layer w0.09: U1.AC21@36.5,57.2 36.5,56.6 37.225,55.875 38,55.875 38.15,55.725 38.55,55.725
  Top Layer w0.12: 38.55,55.725 39.375,54.9 39.375,51.325 43.975,46.725 63.65,46.725 69.25,52.325 69.25,55.2 69.5,55.45 70.925,55.45 71.075,55.6 71.075,56.225 71.225,56.375 71.975,56.375 72.1,56.5 72.1,56.775 71.975,56.9 70.325,56.9 70.08,57.145 70.08,61.202 70.628,61.75 75.875,61.75 76.22,62.095 76.98,62.095 U6.H7@77.75,61.325
DDR_DQ30: U1.AA23 U6.G2 | length 63.4
  Top Layer w0.09: U1.AA23@37.5,58.2 37.885,58.2 38.56,57.525 39.8,57.525
  Top Layer w0.12: 39.8,57.525 41.8,55.525 41.8,53.4 45.7,49.5 60.2,49.5 60.325,49.625 60.325,49.95 60.2,50.075 59.85,50.075 59.75,50.175 59.75,50.4 60.675,51.325 63.35,51.325 65.075,53.05 65.075,55.325 67.42,57.67 67.42,62.959 69.82,65.359 69.82,67.62 71.035,68.835 76.456,68.835 78.185,67.106 78.185,65.93 78.35,65.765 78.4,65.765 78.55,65.615 U6.G2@78.55,65.325
DDR_DQ31: U1.AA22 U6.H3 | length 63.2
  Top Layer w0.09: U1.AA22@37,58.2 37.25,57.95 37.875,57.95 38.55,57.275 39.55,57.275
  Top Layer w0.12: 39.55,57.275 41.425,55.4 41.425,52.975 45.325,49.075 60.575,49.075 60.75,49.25 60.75,49.8 60.875,49.925 62.05,49.925 62.2,50.075 62.2,50.25 62.05,50.4 60.825,50.4 60.675,50.55 60.675,50.725 60.8,50.85 63.475,50.85 65.5,52.875 65.5,55.15 67.84,57.49 67.84,62.785 69.18,64.125 69.975,64.125 70.1,64.25 70.1,64.475 69.925,64.65 69.925,64.87 70.055,65 70.25,65 70.7,64.55 70.7,64.2 70.825,64.075 75.2,64.075 75.575,63.7 77.8,63.7 78.1,64 78.1,64.45 78.025,64.525 U6.H3@77.75,64.525
DDR_DQM0: U1.H23 U2.D3 | length 45.1
  Top Layer w0.09: U1.H23@37.5,64.7 38.55,64.7 39.15,65.3 41.95,65.3
  Top Layer w0.12: 41.95,65.3 42.125,65.475 43.775,65.475 44.16,65.09 44.16,63.615 44.25,63.525 44.475,63.525 44.6,63.65 44.6,64.75 44.685,64.835 46.722,64.835 46.982,64.575 47.08,64.575 47.155,64.65 47.155,65.617 48.253,66.715 54.99,66.715 55.125,66.85 55.125,66.95 54.95,67.125 54.075,67.125 53.95,67.25 53.95,67.375 54.145,67.57 58.88,67.57 63.885,62.565 63.885,60.151 63.674,59.94 62.874,59.94 61.775,58.841 61.775,57.95 61.675,57.85 61.3,57.85 61.125,58.025 U2.D3@61.125,60.3 ; U2.D3@61.105,60.343 U2.D3@61.128,60.32
DDR_DQM1: U1.V22 U2.E7 | length 34.3
  Top Layer w0.09: U1.V22@37,59.7 37.169,59.7 37.249,59.78 37.988,59.78 38.103,59.665 38.16,59.665 38.725,59.1 41.875,59.1
  Top Layer w0.12: 41.875,59.1 44.65,56.325 44.65,54.625 46.7,52.575 48.55,52.575 48.8,52.825 48.8,57.55 50,58.75 60,58.75 60.525,58.225 60.525,57.3 U2.E7@60.325,57.1
DDR_DQM2: U1.C23 U6.D3 | length 63.8
  Top Layer w0.09: U1.C23@37.5,67.2 37.975,67.2 38.5,67.725 39.375,67.725
  Top Layer w0.12: 39.375,67.725 43.7,72.05 61.575,72.05 62.975,70.65 63.75,70.65 64.6,71.5 65.775,71.5 65.9,71.625 65.9,72.05 66.05,72.2 66.45,72.2 66.575,72.075 66.575,71.55 66.75,71.375 67.263,71.375 67.325,71.313 67.325,70.8 67.475,70.65 67.7,70.65 67.85,70.8 67.85,70.95 68.7,71.8 68.7,72.125 68.8,72.225 70.45,72.225 70.55,72.125 70.55,71.925 70.675,71.8 77.8,71.8 78.766,70.834 79.415,70.834 79.624,70.625 79.86,70.625 80.51,69.975 80.51,69.764 82.244,68.03 82.455,68.03 83.71,66.775 83.71,64.241 83.149,63.68 80.855,63.68 80.275,63.1 79.775,63.1 79.55,63.325 79.55,63.825 79.8,64.075 80.55,64.075 U6.D3@80.95,64.475
DDR_DQM3: U1.AA20 U6.E7 | length 63.4
  Top Layer w0.09: U1.AA20@36,58.2 36.25,57.95 36.589,57.95 36.75,57.789 36.75,57.611 36.911,57.45 37.125,57.45 37.25,57.325 37.25,56.925 37.55,56.625 38.2,56.625 38.375,56.45 39.225,56.45
  Top Layer w0.12: 39.225,56.45 40.45,55.225 40.45,52.35 44.8,48 63.1,48 64.35,49.25 64.35,49.425 64.1,49.675 64.1,49.85 66.1,51.85 66.925,51.85 67.975,52.9 67.975,56.1 68.89,57.015 68.89,62.35 69.615,63.075 74.75,63.075 74.9,62.925 79.1,62.925 80.15,61.875 U6.E7@80.15,61.325
DDR_DQS0_N: U1.G23 U2.B7 | length 45.8
  Top Layer w0.1: U1.G23@37.5,65.2 38.4,65.2 38.98,65.78 41.705,65.78 41.93,66.005 44.17,66.005 44.7,65.475 46.445,65.475 46.515,65.545 46.515,65.71 44.795,67.43 44.795,67.715 45.125,68.045 45.43,68.045 46.945,66.53 47.163,66.53 47.988,67.355 48.805,67.355 48.945,67.495 48.945,67.95 49.205,68.21 49.7,68.21 49.815,68.095 49.815,67.51 49.97,67.355 50.85,67.355 51.075,67.58 51.075,67.975 51.31,68.21 51.815,68.21 51.95,68.075 51.95,67.55 52.145,67.355 52.605,67.355 53.46,68.21 59.145,68.21 64.525,62.83 64.525,59.52 64.305,59.3 63.23,59.3 62.445,58.515 62.445,57.38 U2.B7@62.725,57.1
DDR_DQS0_P: U1.G22 U2.C7 | length 45.9
  Top Layer w0.1: U1.G22@37,65.2 37.25,64.95 37.655,64.95 37.675,64.97 38.52,64.97 39.1,65.55 41.8,65.55 42.025,65.775 44.075,65.775 44.605,65.245 46.54,65.245 46.745,65.45 46.745,65.805 45.025,67.525 45.025,67.62 45.22,67.815 45.335,67.815 46.85,66.3 47.258,66.3 48.083,67.125 48.9,67.125 49.175,67.4 49.175,67.855 49.3,67.98 49.5,67.98 49.58,67.9 49.585,67.9 49.585,67.415 49.875,67.125 50.945,67.125 51.305,67.485 51.305,67.88 51.405,67.98 51.625,67.98 51.72,67.885 51.72,67.455 52.05,67.125 52.7,67.125 53.555,67.98 59.05,67.98 64.295,62.735 64.295,59.615 64.21,59.53 63.135,59.53 62.215,58.61 62.215,57.39 U2.C7@61.925,57.1
DDR_DQS1_N: U1.U23 U2.G3 | length 33.8
  Top Layer w0.1: U1.U23@37.5,60.2 38.141,60.2 38.271,60.07 38.355,60.07 38.85,59.575 42.5,59.575 42.855,59.93 43.445,59.93 43.725,59.65 43.725,59.125 43.375,58.775 43.375,58.475 45.25,56.6 45.25,54.85 46.975,53.125 48.025,53.125 48.175,53.275 48.175,58.25 49.33,59.405 55.37,59.405 55.525,59.25 58.925,59.25 59.075,59.4 59.075,60.05 58.825,60.3 U2.G3@58.725,60.3
DDR_DQS1_P: U1.U22 U2.F3 | length 34.6
  Top Layer w0.1: U1.U22@37,60.2 37.154,60.2 37.399,59.955 37.601,59.955 37.616,59.97 38.046,59.97 38.176,59.84 38.26,59.84 38.775,59.325 42.575,59.325 42.95,59.7 43.35,59.7 43.495,59.555 43.495,59.22 43.145,58.87 43.145,58.38 45.02,56.505 45.02,54.755 46.88,52.895 48.12,52.895 48.405,53.18 48.405,58.155 49.425,59.175 55.275,59.175 55.43,59.02 59.02,59.02 59.305,59.305 59.305,60.08 U2.F3@59.525,60.3
DDR_DQS2_N: U1.B23 U6.B7 | length 64.8
  Top Layer w0.1: U1.B23@37.5,67.7 37.875,67.7 38.325,68.15 39.025,68.15 39.5,68.625 39.5,68.775 43.48,72.755 61.795,72.755 63.22,71.33 63.48,71.33 64.35,72.2 65.025,72.2 65.705,72.88 66.895,72.88 67.275,72.5 67.275,72.15 67.395,72.03 67.805,72.03 67.95,72.175 67.95,72.57 68.305,72.925 71.575,72.925 71.805,72.695 71.805,72.57 71.92,72.455 72.48,72.455 72.575,72.55 72.575,72.72 72.785,72.93 73.495,72.93 73.705,72.72 73.705,72.52 73.77,72.455 74.205,72.455 74.275,72.525 74.275,72.75 74.455,72.93 77.595,72.93 78.955,71.57 79.65,71.57 79.955,71.265 80.125,71.265 81.15,70.24 81.15,70.029 82.509,68.67 82.757,68.67 84.25,67.177 84.25,63.455 83.835,63.04 81.24,63.04 81.025,62.825 81.025,62.525 81.25,62.3 81.975,62.3 82.27,62.005 82.27,61.925 82.27,61.605 U6.B7@82.55,61.325
DDR_DQS2_P: U1.C22 U6.C7 | length 65
  Top Layer w0.1: U1.C22@37,67.2 37.25,67.45 37.625,67.45 37.645,67.47 37.97,67.47 38.42,67.92 39.12,67.92 39.73,68.53 39.73,68.68 43.575,72.525 61.7,72.525 63.125,71.1 63.575,71.1 64.445,71.97 65.12,71.97 65.8,72.65 66.8,72.65 67.045,72.405 67.045,72.055 67.3,71.8 67.9,71.8 68.18,72.08 68.18,72.475 68.4,72.695 71.48,72.695 71.575,72.6 71.575,72.475 71.825,72.225 72.575,72.225 72.805,72.455 72.805,72.625 72.88,72.7 73.4,72.7 73.475,72.625 73.475,72.425 73.675,72.225 74.3,72.225 74.505,72.43 74.505,72.62 74.585,72.7 77.5,72.7 78.859,71.34 79.555,71.34 79.86,71.035 80.03,71.035 80.92,70.145 80.92,69.934 82.414,68.44 82.662,68.44 84.02,67.082 84.02,63.55 83.74,63.27 81.145,63.27 80.795,62.92 80.795,62.43 81.155,62.07 81.88,62.07 82.04,61.91 82.04,61.615 U6.C7@81.75,61.325
DDR_DQS3_N: U1.AB23 U6.G3 | length 62.7
  Top Layer w0.1: U1.AB23@37.5,57.7 37.75,57.7 38.425,57.025 39.4,57.025 41.05,55.375 41.05,52.675 45.075,48.65 61.975,48.65 65.85,52.525 66.65,52.525 67.325,53.2 67.325,54.125 67.1,54.35 66.95,54.35 66.855,54.255 66.855,53.405 66.57,53.12 66.23,53.12 65.945,53.405 65.945,54.995 68.25,57.3 68.25,62.616 69.309,63.675 75.1,63.675 75.35,63.425 78.23,63.425 78.84,64.035 78.84,64.235 U6.G3@78.55,64.525
DDR_DQS3_P: U1.AB22 U6.F3 | length 63.7
  Top Layer w0.1: U1.AB22@37,57.7 37.15,57.7 37.405,57.445 37.68,57.445 38.33,56.795 39.28,56.795 40.82,55.255 40.82,52.58 44.98,48.42 62.07,48.42 65.945,52.295 66.745,52.295 67.555,53.105 67.555,54.22 67.195,54.58 66.855,54.58 66.625,54.35 66.625,53.5 66.475,53.35 66.325,53.35 66.175,53.5 66.175,54.9 68.48,57.205 68.48,62.52 69.405,63.445 75.005,63.445 75.255,63.195 78.325,63.195 79.07,63.94 79.07,64.245 U6.F3@79.35,64.525
DDR_ODT: R25.1 U1.L22 U2.K1 U6.K1 | length 72.1
  Top Layer w0.09: U1.L22@37,63.2 37.161,63.2 37.401,62.96 37.599,62.96 37.602,62.963 37.605,62.96 37.675,63.03 39.817,63.03 39.857,63.07 40.143,63.07 40.413,62.8 v1(41.225,62.8)
  Top Layer w0.12: v1@55.925,61.5 U2.K1@56.325,61.9 ; v1(75.75,65.725) U6.K1@76.15,66.125
  Bottom Layer w0.12: v1(41.225,62.8) 41.425,62.6 42.525,62.6 43.475,63.55 43.475,66.575 42.75,67.3 42.75,70.13 42.965,70.345 43.275,70.345 43.38,70.45 43.38,71.095 43.2,71.275 42.9,71.275 42.795,71.38 42.795,71.67 43.425,72.3 47.019,72.3 47.375,71.944 47.375,61.175 49.4,59.15 54.25,59.15 55.525,60.425 55.525,60.809 55.776,61.06 55.785,61.06 55.95,61.225 v1(55.95,61.475) 56.412,61.475 56.562,61.325 57.05,61.325 57.275,61.1 64.675,61.1 66.95,63.375 74.075,63.375 75.35,64.65 75.35,65.05 75.75,65.45 v1(75.75,65.725) 76.11,66.085 76.699,66.085 76.739,66.045 77.266,66.045 78.026,65.285 79.215,65.285 79.75,64.75 R25.1@80.8,64.75
DDR_RASN: R20.1 U1.N21 U2.J3 U6.J3 | length 73.2
  Top Layer w0.09: U1.N21@36.5,62.2 36.75,62.45 39.45,62.45 39.75,62.15 40.15,62.15 v1(40.5,61.8)
  Top Layer w0.1: U2.J3@57.105,60.314 U2.J3@57.106,60.312
  Top Layer w0.12: U2.J3@57.125,60.3 v1(57.525,59.9) ; U6.J3@76.95,64.525 v1(77.35,64.125)
  Bottom Layer w0.12: v1(40.5,61.8) 41.175,61.8 41.825,61.15 44.775,61.15 44.975,61.35 44.975,62.25 44.825,62.4 44.825,62.65 45.15,62.975 45.15,63.425 44.975,63.6 44.975,70.125 45.15,70.3 45.65,70.3 45.85,70.1 45.85,61.125 48.9,58.075 57.375,58.075 57.65,58.35 57.65,58.85 57.3,59.2 57.3,59.675 v1(57.525,59.9) 57.825,59.9 59.35,58.375 64.225,58.375 68.15,62.3 76.475,62.3 77.35,63.175 v1(77.35,64.125) 78.325,64.125 79.625,62.825 79.625,61.85 80.375,61.1 80.5,61.1 80.8,60.8 R20.1@80.8,60.75
DDR_RESETN: R28.2 U1.D20 U2.T2 U6.T2 | length 62
  Top Layer w0.09: U1.D20@36,66.7 36.25,66.95 36.25,67.3 36.4,67.45 36.589,67.45 36.75,67.611 36.75,67.789 36.911,67.95 37.089,67.95 37.25,68.111 37.25,68.325 37.645,68.72 38.52,68.72 v1(38.625,68.825)
  Top Layer w0.12: v1(51.125,62.44) 51.125,61.5 U2.T2@51.525,61.1 ; v1(70.97,66.935) 70.97,66.275 70.99,66.255 70.99,65.976 71.36,65.606 U6.T2@71.36,65.285
  Bottom Layer w0.12: v1(38.625,68.825) 38.625,76 39.675,77.05 50.7,77.05 51.125,76.625 51.125,66.525 51.125,65.85 ; v1(51.125,62.44) 51.125,65.85 ; v1(70.97,66.935) 56.21,66.935 55.125,65.85 51.125,65.85
DDR_WEN: R24.1 U1.M20 U2.L3 U6.L3 | length 71.8
  Top Layer w0.12: v1(35.125,63.45) 35.575,63 35.7,63 U1.M20@36,62.7 ; U2.L3@55.525,60.3 v1(55.925,59.9) ; U6.L3@75.35,64.525 v1(75.75,64.125)
  Bottom Layer w0.12: v1(35.125,63.45) 35.65,62.925 38.875,62.925 39.25,62.55 39.55,62.55 39.735,62.365 40.149,62.365 40.184,62.4 41.211,62.4 41.846,61.765 42.615,61.765 44.2,63.35 44.2,70.65 44.7,71.15 46.05,71.15 46.625,70.575 46.625,61.175 49.225,58.575 54.6,58.575 v1(55.925,59.9) 56.325,60.3 56.875,60.3 57.1,60.525 58.175,60.525 58.75,59.95 61.525,59.95 61.935,59.54 64.215,59.54 67.475,62.8 74.425,62.8 76.15,64.525 76.7,64.525 76.925,64.75 78.8,64.75 R24.1@80.8,62.75
eMMC_SDIO2_D0: U1.C13 U5.A3 | length 19.1
  Top Layer w0.09: U5.A3@31.2,84.475 31.55,84.125 ; 32.25,68.625 32.25,67.45 U1.C13@32.5,67.2
  Top Layer w0.13: 31.55,84.125 32.55,84.125 32.775,83.9 32.775,73.25 31.925,72.4 31.925,70.575 32.25,70.25 32.25,68.625
eMMC_SDIO2_D1: U1.B12 U5.A4 | length 19.1
  Top Layer w0.09: 30.7,84.1 U5.A4@30.7,84.475 ; U1.B12@32,67.7 32,69.925
  Top Layer w0.13: 30.7,84.1 31.2,83.6 31.2,82.575 31.4,82.375 32.125,82.375 32.35,82.15 32.35,78.075 31.6,77.325 31.6,76.875 32.35,76.125 32.35,73.65 31.5,72.8 31.5,70.425 32,69.925
eMMC_SDIO2_D2: U1.A11 U5.A5 | length 19
  Top Layer w0.09: 30.2,83.275 U5.A5@30.2,84.475 ; U1.A11@31.5,68.2 31.5,69.45
  Top Layer w0.13: 30.2,83.275 30,83.075 30,82.5 31.45,81.05 31.45,80.725 30.675,79.95 30.675,79.75 31.45,78.975 31.45,78.65 30.625,77.825 30.625,76.25 31.525,75.35 31.525,74.3 30.65,73.425 30.65,70.3 31.5,69.45
eMMC_SDIO2_D3: U1.B13 U5.B2 | length 19.9
  Top Layer w0.09: U5.B2@31.7,84.975 31.725,84.975 31.965,85.215 32.51,85.215 32.525,85.2 ; U1.B13@32.5,67.7 32.75,67.95 32.75,68.6 ; 33.4,85.2 33.425,85.2
  Top Layer w0.13: 32.525,85.2 33.4,85.2 ; 32.775,68.6 32.775,71.941 33.675,72.841 33.675,84.95 33.425,85.2
eMMC_SDIO2_D4: U1.A13 U5.B3 | length 18.9
  Top Layer w0.09: U5.B3@31.2,84.975 31.2,84.965 31.45,84.715 32.515,84.715
  Top Layer w0.13: U1.A13@32.5,68.2 32.5,72.25 33.25,73 33.25,84.55 33.085,84.715 32.515,84.715
eMMC_SDIO2_D5: U1.B10 U5.B4 | length 19.2
  Top Layer w0.09: 30.65,69.075 30.76,68.965 30.76,67.94 U1.B10@31,67.7 ; U5.B4@30.7,84.975 30.95,84.725 30.95,84.275
  Top Layer w0.13: v1(29.375,80.1) 29.375,70.35 30.65,69.075 ; 30.95,84.275 31.575,83.65 v1(31.575,82.875)
  Bottom Layer w0.13: v1(29.375,80.1) 31.575,82.3 v1(31.575,82.875)
eMMC_SDIO2_D6: U1.C11 U5.B5 | length 19
  Top Layer w0.09: 29.95,83.55 29.95,84.725 U5.B5@30.2,84.975 U5.B5@30.2,84.965 ; 31.25,69.35 31.25,67.45 U1.C11@31.5,67.2
  Top Layer w0.13: 29.95,83.55 29.65,83.25 29.65,82.275 30.225,81.7 30.225,75.9 30.525,75.6 30.525,74.375 30.225,74.075 30.225,70.375 31.25,69.35
eMMC_SDIO2_D7: U1.B11 U5.B6 | length 20.7
  Top Layer w0.09: U5.B6@29.7,84.975 29.95,85.225 30.325,85.225 30.45,85.1 30.45,83.85 ; U1.B11@31.5,67.7 31.74,67.94 31.74,69.635
  Top Layer w0.13: 30.45,83.85 30.875,83.425 30.875,82.275 31.175,81.975 31.8,81.975 31.925,81.85 31.925,78.375 31.125,77.575 31.125,76.5 31.925,75.7 31.925,74 31.075,73.15 31.075,70.3 31.74,69.635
